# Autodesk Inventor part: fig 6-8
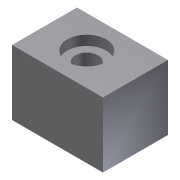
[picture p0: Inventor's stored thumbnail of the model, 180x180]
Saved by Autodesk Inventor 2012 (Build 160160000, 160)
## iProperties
Created: 2009-09
Part Number: fig 6-8
Document SubType Name: Modeling
Designer: Sham
Density: 1 g/cm^3
Material: Default
Author: Sham
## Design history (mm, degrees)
sketch "Sketch1"
  geometry: L1 (-28, 20)-(0, 20); L2 (0, 20)-(0, 0); L3 (0, 0)-(-28, 0); L4 (-28, 0)-(-28, 20)
  constraints: 8 end point, 2 parallel, 1 horizontal, 1 perpendicular
extrude "Extrusion1" new body sketch "Sketch1" distance "d0" = 20; taper "d1" = 0 deg
hole "Hole1" diameter "d4" = 7; stored, may be unused: countersink angle "d8" = 90 deg, drill point angle "d10" = 118 deg; dims "d2" = 10, "d3" = 15, "d5" = 6, "d6" = 12, "d7" = 3, "d9" = 15
body "Solid1"
